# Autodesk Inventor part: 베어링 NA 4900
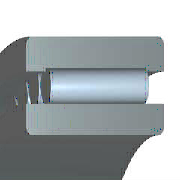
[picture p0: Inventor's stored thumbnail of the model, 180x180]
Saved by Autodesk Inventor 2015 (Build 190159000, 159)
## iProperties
Created: 2009-02
Part Number: 베어링 NA 4900
Material: Steel, Mild
Description: 니들 롤러 베어링 - 경계 치수 및 공차
Document SubType Name: Modeling
Standard: KS B 2029
Designer: SeoGD™
Standards Organization: KS
Language: ko-KR
Size Designation: NA 4900 - 10 x 22 x 13
Categories: <MemberInstance><Categories><Category DisplayName="샤프트 부품" InternalName="7f7aeb1f-a693-4053-b835-cee3144e0d98" Mnemonic="SHFT"><Category DisplayName="베어링" Inter
Density: 7.86 g/cm^3
Appearance: Metal-Steel
Mass: 23.8213 g
Surface Area: 38.613 cm^2
Volume: 3.0307 cm^3
IsCustomPart: 0
Author: SeoGD™
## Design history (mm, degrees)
sketch "스케치"
  geometry: L1 (1.857, 9)-(11.143, 9); L2 (11.143, 9)-(11.143, 7); L3 (13, 7)-(0, 7); L4 (1.857, 7)-(1.857, 9); L5 (1.857, 8)-(11.143, 8); L6 (6.5, 8)-(6.5, 7); L7 (0, 5)-(13, 5); L8 (0, 11)-(13, 11); L9 (13, 5)-(13, 7); L10 (13, 8.8)-(13, 11); L11 (1.857, 8.8)-(0, 8.8); L12 (11.143, 8.8)-(13, 8.8); L13 (-6, 0)-(36, 0) reference; L14 (0, -1.9)-(0, 14.9) reference
  constraints: 24 end point, 8 point on line, 3 midpoint, 3 parallel, 3 perpendicular, 2 symmetric about line, 1 horizontal, 1 other
  dimensions: "d6" = 10 diameter of L7 L13 (= WD); "d7" = 14 diameter of L3 L13 (= KID1); "d8" = 22 diameter of L8 L13 (= BD); "d9" = 16 diameter of L6.start L13 (= 0.5 x WD + 0.5 x BD); "d10" = 17.6 diameter of L12 L13 (= 0.9 x BD + 0.9 x WD - 0.8 x KID1); "d11" = 18 diameter of L1 L13 (= BD + WD - KID1); "d12" = 1.85714 distance between parallel lines of L14 L4 (= 0.142857 x KB); "d13" = 13 distance between parallel lines of L14 L9 (= KB); "d14" = 11.14286 distance between parallel lines of L14 L2 (= 0.857143 x KB)
revolve "본체" stored, may be unused: angle "d17" = 90 deg
revolve "롤러" stored, may be unused: angle "d18" = 90 deg
pattern_circular "IDS_ARRAYROLLER[SIMPL:T]" dims angle "d2" = 360 deg
body "Solid1"
fillet "모깎기1" dims "d0" = 0.3 (= KRS)
other parameters: "WD" = 10 [user parameter; used in 6 equation terms], "BD" = 22 [user parameter; used in 6 equation terms], "KB" = 13 [user parameter; used in 3 equation terms], "KID1" = 14 [user parameter; used in 4 equation terms], "KRS" = 0.3 [user parameter; used in 1 equation term], "d3" = 0, "d4" = 0, "d5" = 0, "d15" = 0, "d16" = 0, "BC0" = 9150000 [user parameter], "WR" = 5 (= 0.5 x WD) [user parameter], "BBA" = 0 [user parameter], "BC" = 8150000 [user parameter], "BR" = 11 (= 0.5 x BD) [user parameter]
